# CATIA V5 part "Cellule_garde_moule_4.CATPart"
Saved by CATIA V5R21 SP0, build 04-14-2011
Part number: Moule_cellule_garde
Bounding box of the stored display mesh (mm): x -18 to 18, y -72 to 72, z -15 to 0
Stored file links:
  C:\Users\zerma\Pictures\Moule_2\Cellule_garde_moule_4.CATPart
  Product1.CATProduct
  C:\Users\zerma\Pictures\Moule\Moule_v1.CATPart
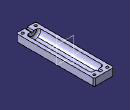
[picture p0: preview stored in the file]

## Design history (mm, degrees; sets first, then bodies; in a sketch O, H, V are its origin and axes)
Body1 (main body)
  Sketch1 on yz-plane, origin (0, 0, 0), H (0, 1, 0), V (0, 0, 1)
    line L1 (-95, -12.5) -> (95, -12.5)
    point P1 (-95, -12.5)
    line L2 (-100, -15) -> (100, -15)
    point P3 (-100, -15)
    line L3 (-95, -12.5) -> (-95, 0)
    point P5 (-95, 0)
    line L4 (-100, -15) -> (-100, 0)
    point P6 (-100, 0)
    line L5 (-95, 0) -> (-100, 0)
    point P7 (100, 0)
    point P8 (100, -15)
    line L6 (100, -15) -> (100, 0)
    point P9 (95, 0)
    line L7 (95, 0) -> (100, 0)
    point P10 (95, -12.5)
    line L8 (95, -12.5) -> (95, 0)
    distance L1 H = 12.5
    distance L1 L2 = 2.5
    length L4 = 15
    distance L4 L3 = 5
    length L1 = 190
    length L2 = 200
    distance V L3 = 95
    horizontal: L1 H, L2 H, L5 H
    vertical: L3 V, L4 V
    symmetry: P6 P7 V, P3 P8 V, L4 L6 V, P5 P9 V, L5 L7 V, P1 P10 V, L3 L8 V
  Shaft1: profile Sketch1, axis Sketch1.H, angle 360
  Sketch2 on face of Shaft1 from Sketch1.L4, origin (0, -100, 0), H (1, 0, 0), V (0, 0, 1)
    line L1 (-10, 2.5) -> (10, 2.5)
    line L2 (10, 2.5) -> (10, -2.5)
    line L3 (10, -2.5) -> (-10, -2.5)
    line L4 (-10, -2.5) -> (-10, 2.5)
    length L2 = 5
    length L1 = 20
    horizontal: L1 H, L3 H
    vertical: L2 V, L4 V
    symmetry: L3 L1 H, L4 L2 V
  Pad1: profile Sketch2, direction (0, -1, 0), length 15
  Sketch3 on face of Pad1 from Sketch2.L1, origin (0, 0, 2.5), H (1, 0, 0), V (0, 1, 0)
    circle A1 centre (0, -107.5) radius 2.5
    point P1 (0, -107.5)
    reference intersected line E1 (14.7902, -100) -> (-14.7902, -100) from face of Shaft1 from Sketch1.L4
    radius A1 = 2.5
    distance P1 E1 = 7.5
    coincidence: P1 V
  Pocket1: profile Sketch3, direction (0, 0, -1), length 5, mirrored extent
  Fillet1: radius 2, on edge [face of Pad1 from Sketch2.L4 | end face of Pad1]; edge [face of Pad1 from Sketch2.L1 | end face of Pad1]; edge [face of Pad1 from Sketch2.L3 | end face of Pad1]; edge [face of Pad1 from Sketch2.L2 | end face of Pad1]; edge [face of Pad1 from Sketch2.L2 | face of Pad1 from Sketch2.L3]; edge [face of Shaft1 from Sketch1.L4 | face of Pad1 from Sketch2.L3]; edge [face of Pad1 from Sketch2.L3 | face of Pad1 from Sketch2.L4]; edge [face of Pocket1 from Sketch3.A1 | face of Pad1 from Sketch2.L3]; edge [face of Pad1 from Sketch2.L4 | face of Pad1 from Sketch2.L1]; edge [face of Pad1 from Sketch2.L1 | face of Pad1 from Sketch2.L2]; edge [face of Shaft1 from Sketch1.L4 | face of Pad1 from Sketch2.L1]; edge [face of Shaft1 from Sketch1.L4 | face of Pad1 from Sketch2.L4]; edge [face of Shaft1 from Sketch1.L4 | face of Pad1 from Sketch2.L2]; face of Pad1 from Sketch2.L1
  Mirror1: of Pad1, Pocket1, Fillet1, about zx-plane
  Fillet2: radius 4, on edge [face of Shaft1 from Sketch1.L2 | face of Shaft1 from Sketch1.L6]; edge [face of Shaft1 from Sketch1.L4 | face of Shaft1 from Sketch1.L2]
Body2
  Sketch4 on xy-plane, origin (0, 0, 0), H (1, 0, 0), V (0, 1, 0)
    line L1 (18, 72) -> (18, -72)
    line L2 (18, -72) -> (-18, -72)
    line L3 (-18, -72) -> (-18, 72)
    line L4 (-18, 72) -> (18, 72)
    length L1 = 144
    length L4 = 36
    vertical: L1 V, L3 V
    horizontal: L2 H, L4 H
    equidistance: L1 L3 O, L2 L4 O
  Pad2: profile Sketch4, direction (0, 0, -1), length 15
  Body3
    Sketch5 on yz-plane, origin (0, 0, 0), H (0, 1, 0), V (0, 0, 1)
      line L1 (-55, -3.5) -> (55, -3.5)
      point P1 (-55, -3.5)
      point P2 (55, -3.5)
      line L2 (-60, -11.5) -> (60, -11.5)
      point P3 (-60, -11.5)
      point P4 (60, -11.5)
      line L3 (-55, -3.5) -> (-55, 0)
      point P5 (-55, 0)
      line L4 (-60, -11.5) -> (-60, -2.5)
      point P6 (-60, -2.5)
      point P7 (60, -2.5)
      point P8 (60, -11.5)
      line L5 (60, -11.5) -> (60, -2.5)
      point P9 (55, 0)
      point P10 (55, -3.5)
      line L6 (55, -3.5) -> (55, 0)
      line L7 (-60, -2.5) -> (-72, -2.5)
      line L8 (-72, -2.5) -> (-72, 0)
      line L9 (-72, 0) -> (-55, 0)
      point P13 (-55, 0)
      line L10 (60, -2.5) -> (67, -2.5)
      line L11 (67, -2.5) -> (67, 0)
      line L12 (67, 0) -> (55, 0)
      distance L1 H = 3.5
      distance L1 L2 = 8
      distance L4 L3 = 5
      distance V L3 = 55
      length L9 = 17
      length L12 = 12
      length L11 = 2.5
      horizontal: L1 H, L2 H, L7 H, L9 H, L10 H, L12 H
      vertical: L3 V, L4 V, L8 V, L11 V
      symmetry: P6 P7 V, P3 P8 V, L4 L5 V, P5 P9 V, P1 P10 V, L3 L6 V
      coincidence: P13 P5, L9 H, P4 P8, P2 P10
    Shaft2: profile Sketch5, axis Sketch5.H, angle 360
  Remove1: tool Body3
  Sketch6 on face of Shaft2 from Sketch5.L6, origin (0, 55, 0), H (-1, 0, 0), V (0, 0, 1)
    circle A1 centre (0, 0) radius 3.5
    reference projected circle E1 centre (0, 0) radius 3.5 from edge [face of Shaft2 from Sketch5.L1 | face of Shaft2 from Sketch5.L6]
    reference projected circle E2 centre (0, 0) radius 3.5 from edge [face of Shaft2 from Sketch5.L1 | face of Shaft2 from Sketch5.L6]
    coincidence: A1 E1
    concentricity: A1 E2
  Pocket2: profile Sketch6, direction (0, -1, 0), up to face of Shaft2 from Sketch5.L3
  Sketch7 on end face of Pad2, origin (0, 0, -15), H (1, 0, 0), V (0, -1, 0)
    circle A1 centre (12, 66) radius 2.25
    point P1 (12, 66)
    circle A2 centre (12, -66) radius 2.25
    circle A3 centre (-12, 66) radius 2.25
    circle A4 centre (-12, -66) radius 2.25
    reference projected line E1 (18, 72) -> (18, -72) from edge [end face of Pad2 | face of Pad2 from Sketch4.L1]
    reference projected line E2 (-18, 72) -> (18, 72) from edge [end face of Pad2 | face of Pad2 from Sketch4.L2]
    radius A1 = 2.25
    distance P1 E1 = 6
    distance P1 E2 = 6
    symmetry: A1 A2 H, A1 A3 V, A3 A4 H
  Pocket3: profile Sketch7, direction (0, 0, 1), length 50, mirrored extent
  Chamfer1: length 2, angle 45, on edge [face of Pad2 from Sketch4.L4 | face of Pad2 from Sketch4.L3]; edge [end face of Pad2 | face of Pad2 from Sketch4.L4]; edge [end face of Pad2 | face of Pad2 from Sketch4.L3]; edge [face of Pad2 from Sketch4.L1 | face of Pad2 from Sketch4.L4]; edge [end face of Pad2 | face of Pad2 from Sketch4.L1]; edge [end face of Pad2 | face of Pad2 from Sketch4.L2]; edge [face of Pad2 from Sketch4.L2 | face of Pad2 from Sketch4.L1]; edge [face of Pad2 from Sketch4.L3 | face of Pad2 from Sketch4.L2]
  Fillet3: radius 4, on edge [face of Shaft2 from Sketch5.L5 | face of Shaft2 from Sketch5.L2]
  Fillet4: radius 4, on edge [face of Shaft2 from Sketch5.L2 | face of Shaft2 from Sketch5.L4]
  CLDGeom1 "Maillage.1"
  CLDGeom2 "Maillage.2"
  CLDGeom3 "Maillage.3"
